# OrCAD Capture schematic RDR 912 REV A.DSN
size Custom; title: 12V 0.2A LNK-TN2-900; rev: A
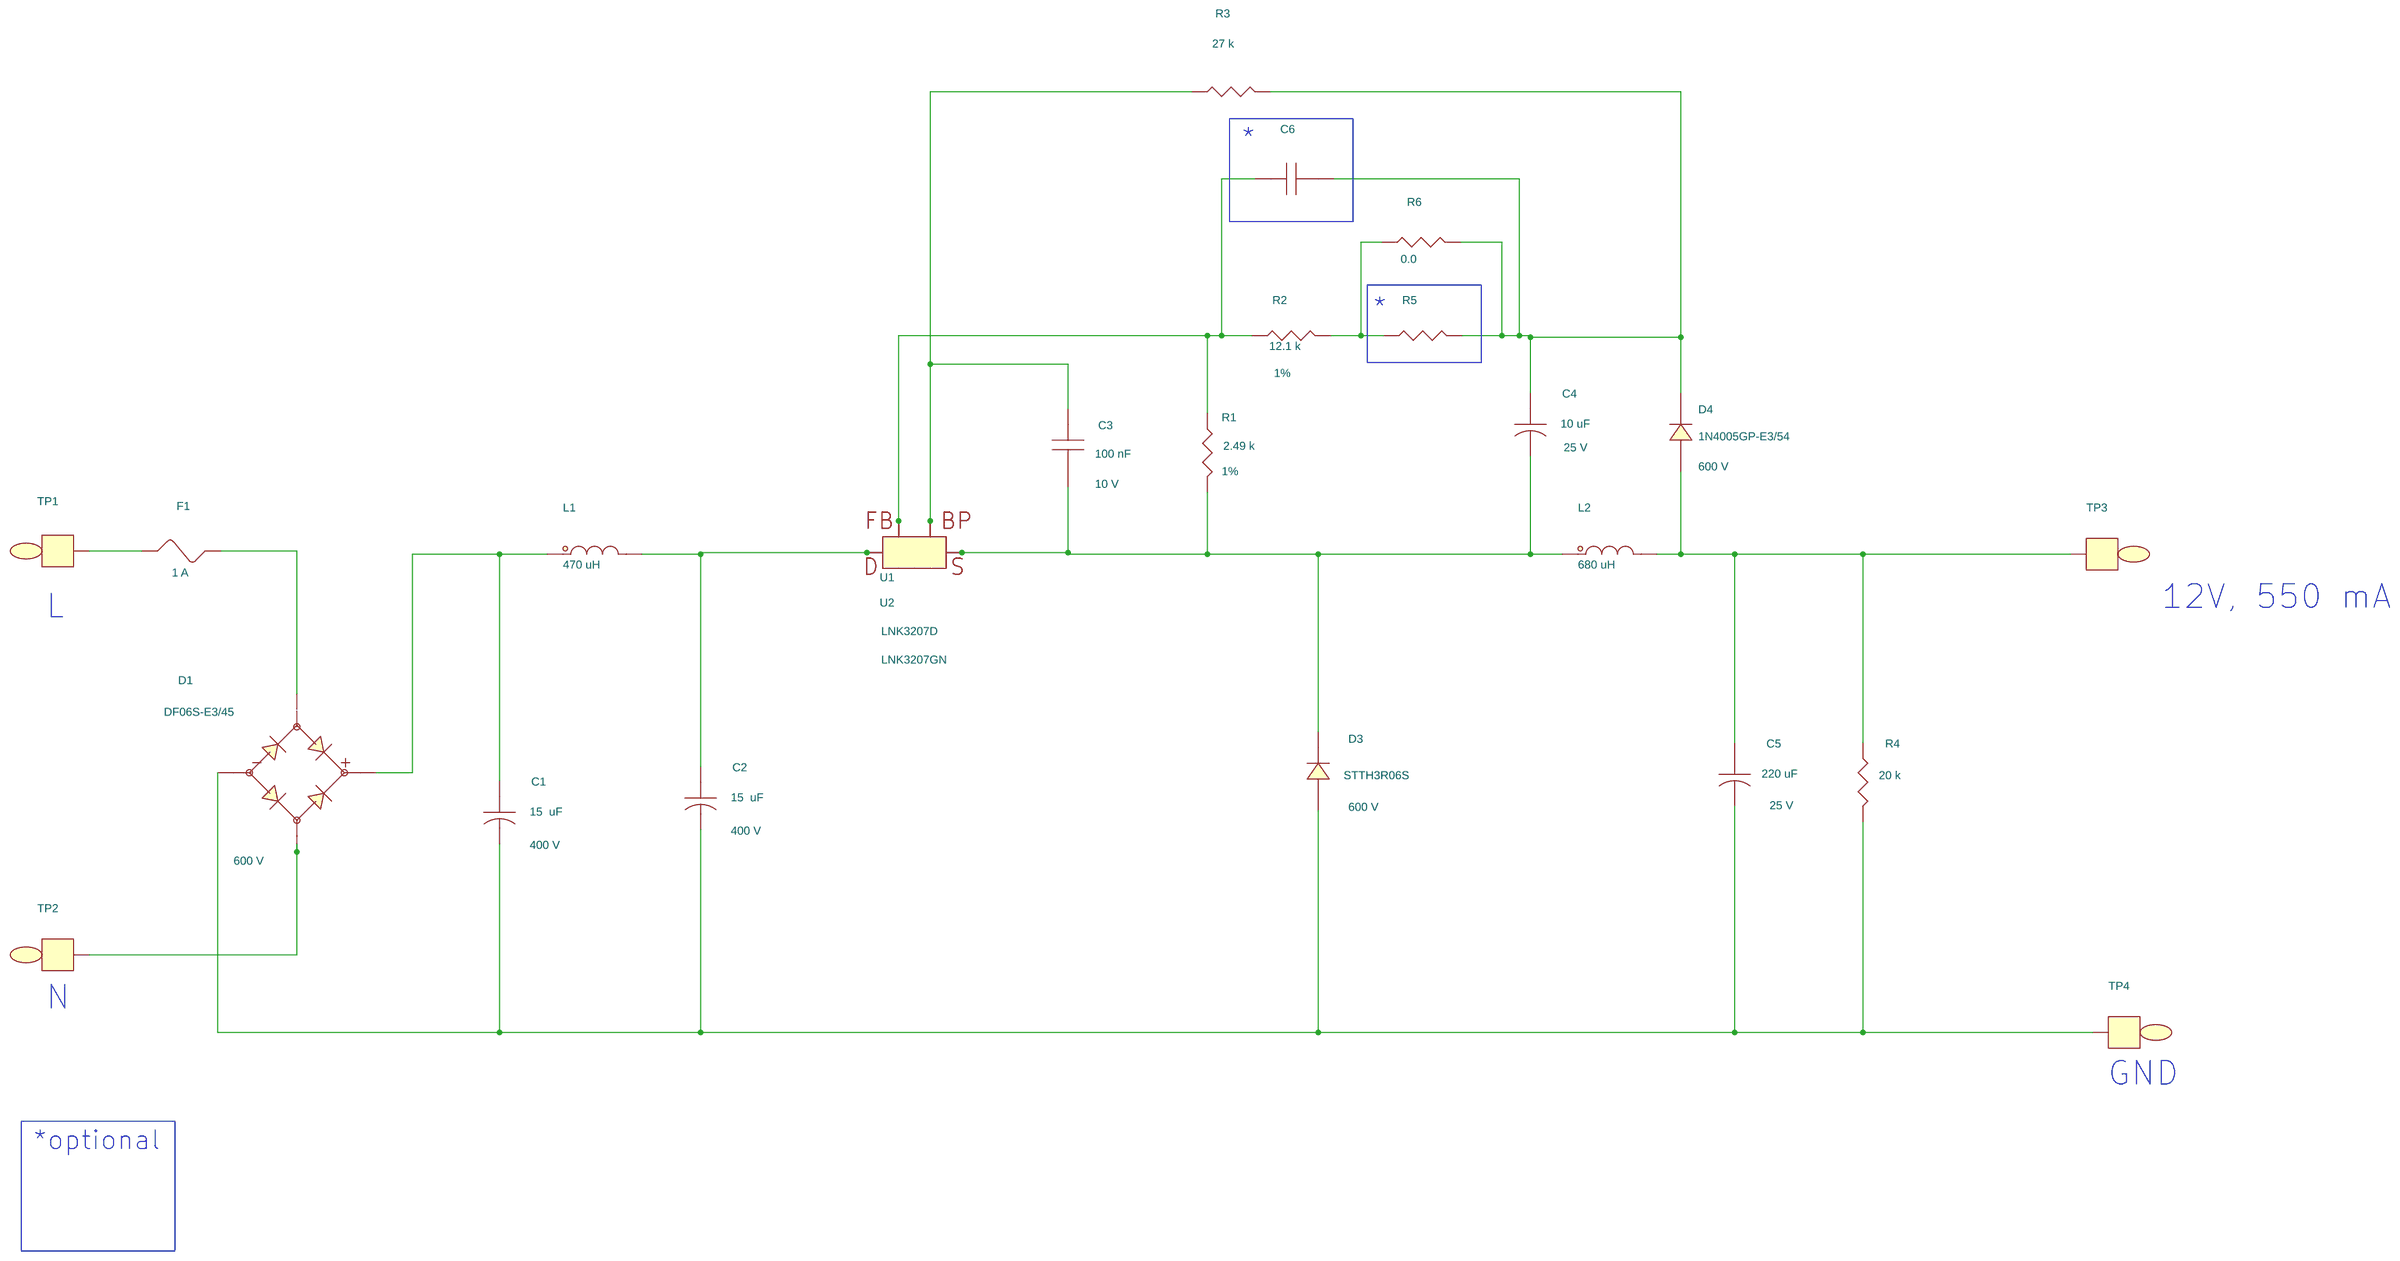
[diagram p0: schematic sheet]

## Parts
C1  15  uF  [PI_POLCAPD8xH16xlLS3p5mm063H]
C2  15  uF  [PI_POLCAPD8xH16xlLS3p5mm063H]
C3  100 nF  [pismc0805]
C4  10 uF  [pipolcapclyd5mmls2mm025]
C5  220 uF  [pipolcapclyd320ls140030]
C6  1000 pF  [pismc0603]
D1  DF06S-E3/45  [pismddfs]
D3  STTH3R06S  [pismdo214ab12]
D4  1N4005GP-E3/54  [pidv200x110x040do41]
F1  1 A  [pi_rst_microfuse]
L1  470 uH  [pi_choke_RL5480-2_d2]
L2  680 uH  [pi_choke_2p_d400ls200d05]
R1  2.49 k  [pismr0603]
R2  12.1 k  [pismr0603]
R3  27 k  [pismr0603]
R4  20 k  [pismr0805]
R5  6.81 k  [pismr0603]
R6  0.0  [pismr0402]
TP1  WHT  [pitpkeystone125x125]
TP2  BLK  [pitpkeystone125x125]
TP3  RED  [pitpkeystone100x100]
TP4  BLK  [pitpkeystone100x100]
U1  LNK3207D  [pismso8dnshort5678]
U2  LNK3207GN  [Piicsmd8cshort5678]

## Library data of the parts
C1 C2 = CAP_POL: ALT_SYMBOLS: PI_POLCAPD8mmxlLS3p5mm063V; Disp_Voltage: 400 V; FPLIST: PI_POLCAPD8xH16xlLS3p5mm063H,PI_POLCAPD8mmxlLS3p5mm063V; Part Number: 20-09026-00; Voltage: 400 V
C3 = CAP_NP: Disp_Voltage: 10 V; Part Number: 20-01399-00; Voltage: 10 V
C4 = CAP_POL: Disp_Voltage: 25 V; Part Number: 20-09124-00; Voltage: 25 V
C5 = CAP_POL: ALT_SYMBOLS: pipolcapclyd320ls140030430h; Disp_Voltage: 25 V; FPLIST: pipolcapclyd320ls140030,pipolcapclyd320ls140030430h,pipolcapclyd320ls140030430h; Part Number: 20-00028-00; Voltage: 25 V
C6 = CAP_NP: Disp_Voltage: 100V; Part Number: 20-09218-00; Voltage: 100V
D1 = DIODE_BRIDGE_+-~~: Disp_Voltage: 600 V; Part Number: 15-00281-00
D3 = DIODE: Disp_Voltage: 600 V; Part Number: 15-00827-00
D4 = DIODE: ALT_SYMBOLS: pidv200x110x040do41A,pidax475x125040do41,pidv200x110x040do41wbead,pidax390x125040do41; Disp_Voltage: 600 V; FPLIST: pidv200x110x040do41,pidv200x110x040do41A,pidax475x125040do41,pidv200x110x040do41wbead,pidax390x125040do41; Part Number: 15-01639-00
F1 = FUSE: ALT_SYMBOLS: pirstmicrofusehoz; FPLIST: pi_rst_microfuse,pirstmicrofusehoz; Part Number: 40-00053-00
L1 = INDUCTOR_DOT2: ALT_SYMBOLS: pi_choke_RL5480-2H_d2; FPLIST: pi_choke_RL5480-2_d2,pi_choke_RL5480-2H_d2; Part Number: 30-00308-00
L2 = INDUCTOR_DOT1: ALT_SYMBOLS: pi_choke_2p_d400ls200d05H; FPLIST: pi_choke_2p_d400ls200d05,pi_choke_2p_d400ls200d05H; Part Number: 30-04128-00
R1 = R: Disp_Tol: 1%; Part Number: 05-01116-00
R2 = R: Disp_Tol: 1%; Part Number: 05-03190-00
R3 = R: Part Number: 05-01722-00
R4 = R: Part Number: 05-01550-00
R5 = R: Disp_Tol: 1%; Part Number: 05-01158-00
R6 = R: ALT_SYMBOLS: RC0402; Part Number: 05-06420-00
TP1 = TESTPOINT: Part Number: 35-00044-00
TP2 = TESTPOINT: Part Number: 35-00042-00
TP3 = TESTPOINT: Part Number: 35-00080-00
TP4 = TESTPOINT: ALT_SYMBOLS: TP_TH_CR2_D1_1; Part Number: 35-00079-00
U1 = LNK32XX_8C: Part Number: 10-01286-00
U2 = LNK32XX_8C: Part Number: 10-01287-00

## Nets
SOURCE: U1.6(SOURCE) U1.7(SOURCE) U1.8(SOURCE) U2.6(SOURCE) U2.7(SOURCE) U2.8(SOURCE)
N4183667: C2.1 L1.1 U1.4(D) U2.4(D)
N4183681: C1.2 C2.2 C5.2 D1.2 D3.2 R4.2 TP4.1
N4183878: C3.2 C4.2 D3.1 L2.1 R1.2 U1.5(S) U2.5(S)
N4183892: C3.1 R3.1 U1.1(BP) U2.1(BP)
N4184371: C6.1 R1.1 R2.1 U1.2(FB) U2.2(FB)
N4185002: C5.1 D4.2 L2.2 R4.1 TP3.1
N4185015: C4.1 C6.2 D4.1 R3.2 R5.2 R6.2
N4189997: F1.2 TP1.1
N4190803: C1.1 D1.1 L1.2
N4191135: D1.3 F1.1
N4191491: D1.4 TP2.1
N4200643: R2.2 R5.1 R6.1

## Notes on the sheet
- *
- *
- 12V, 550 mA
- L
- N
- GND
- *optional
